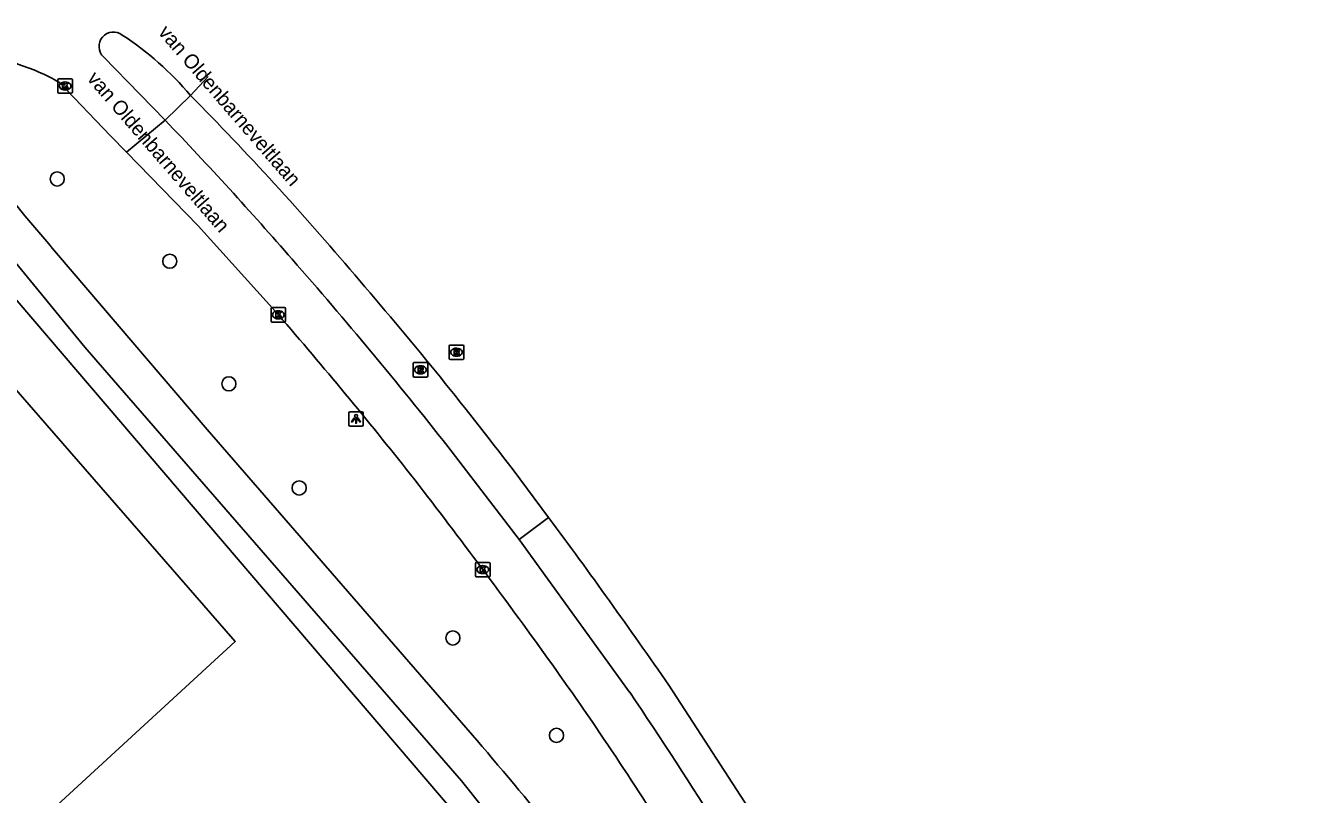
# Model space of a CAD drawing. Extents: x 162417 to 163721, y 384268 to 385416.
# Drawn here: x 163440.1 to 163528.5, y 385162.3 to 385215.4 of the extents above; entities that cross this region are included whole.
import ezdxf

# ---------------------------------------------------------------- set-up
doc = ezdxf.new("R2010")
doc.units = 0
for name, color, linetype in [('IMGEO_Boom', 7, 'Continuous'), ('IMGEO_Fietspad_open', 7, 'Continuous'), ('IMGEO_Gemengd_bos', 7, 'Continuous'), ('IMGEO_Kolk', 7, 'Continuous'), ('IMGEO_Lichtpunt', 7, 'Continuous'), ('IMGEO_Openbare_ruimte_label', 7, 'Continuous'), ('IMGEO_Rijbaan_lokaal_gesloten', 7, 'Continuous'), ('IMGEO_Rijbaan_lokaal_open', 7, 'Continuous'), ('IMGEO_Rioolput', 7, 'Continuous'), ('IMGEO_Verkeerseiland_open', 7, 'Continuous'), ('IMGEO_Voetpad_open', 7, 'Continuous')]:
    doc.layers.add(name, color=color, linetype=linetype)

msp = doc.modelspace()

# ---------------------------------------------------------------- linework, layer by layer
at = {"layer": 'IMGEO_Boom'}
for centre in [(163442.28, 385204.844), (163450.063, 385199.158), (163454.148, 385190.69), (163459.007, 385183.495), (163469.632, 385173.133), (163476.798, 385166.404)]:
    msp.add_circle(centre, 0.489, dxfattribs=at)
at = {"layer": 'IMGEO_Fietspad_open'}
for points in [[(163431.787, 385208.07), (163431.922, 385207.954), (163432.159, 385207.714), (163433.841, 385205.808), (163444.2, 385193.223), (163470.237, 385163.265), (163478.767, 385152.569), (163484.279, 385144.583), (163488.178, 385138.38), (163494.183, 385128.236), (163502.766, 385111.711), (163507.809, 385101.794), (163517.384, 385082.877), (163528.502, 385060.963)], [(163442.24, 385199.707), (163452.646, 385187.546), (163471.281, 385166.067)]]:
    msp.add_lwpolyline(points, dxfattribs=at)
for centre, radius, start, end in [((163733.724, 385447.945), 382.864, 218.38399, 220.41896), ((163318.814, 385033.841), 201.816, 35.81358, 40.93323)]:
    msp.add_arc(centre, radius, start, end, dxfattribs=at)
at = {"layer": 'IMGEO_Gemengd_bos'}
msp.add_lwpolyline([(163309.738, 385096.794), (163334.35, 385105.91), (163401.172, 385130.32), (163403.611, 385131.145), (163408.387, 385133.189), (163412.924, 385135.721), (163417.172, 385138.714), (163421.083, 385142.134), (163454.583, 385172.899), (163428.403, 385202.907)], dxfattribs=at)
at = {"layer": 'IMGEO_Kolk'}
for p, q in [((163442.327, 385210.842), (163442.327, 385211.694)), ((163442.402, 385211.768), (163443.254, 385211.768)), ((163442.815, 385211.548), (163442.84, 385211.548)), ((163443.328, 385211.694), (163443.328, 385210.842)), ((163443.254, 385210.768), (163442.402, 385210.768)), ((163442.838, 385210.988), (163442.813, 385210.988)), ((163457.064, 385195.034), (163457.064, 385195.886)), ((163457.139, 385195.96), (163457.991, 385195.96)), ((163457.552, 385195.74), (163457.577, 385195.74)), ((163458.065, 385195.886), (163458.065, 385195.034)), ((163457.991, 385194.96), (163457.139, 385194.96)), ((163457.575, 385195.18), (163457.55, 385195.18)), ((163471.2, 385177.43), (163471.2, 385178.282)), ((163471.275, 385178.356), (163472.127, 385178.356)), ((163471.688, 385178.136), (163471.713, 385178.136)), ((163472.201, 385178.282), (163472.201, 385177.43)), ((163472.127, 385177.356), (163471.275, 385177.356)), ((163471.711, 385177.576), (163471.686, 385177.576))]:
    msp.add_line(p, q, dxfattribs=at)
for points in [[(163442.327, 385210.842), (163442.327, 385211.694)], [(163442.402, 385211.768), (163443.254, 385211.768)], [(163442.648, 385211.468), (163442.771, 385211.468), (163442.771, 385211.317), (163442.901, 385211.468), (163443.065, 385211.468), (163442.919, 385211.317), (163443.072, 385211.068), (163442.92, 385211.068), (163442.835, 385211.232), (163442.771, 385211.165), (163442.771, 385211.068), (163442.648, 385211.068), (163442.648, 385211.468)], [(163443.328, 385211.694), (163443.328, 385210.842)], [(163443.254, 385210.768), (163442.402, 385210.768)], [(163457.064, 385195.034), (163457.064, 385195.886)], [(163457.139, 385195.96), (163457.991, 385195.96)], [(163457.385, 385195.66), (163457.508, 385195.66), (163457.508, 385195.509), (163457.638, 385195.66), (163457.802, 385195.66), (163457.656, 385195.509), (163457.809, 385195.26), (163457.657, 385195.26), (163457.572, 385195.424), (163457.508, 385195.357), (163457.508, 385195.26), (163457.385, 385195.26), (163457.385, 385195.66)], [(163458.065, 385195.886), (163458.065, 385195.034)], [(163457.991, 385194.96), (163457.139, 385194.96)], [(163471.2, 385177.43), (163471.2, 385178.282)], [(163471.275, 385178.356), (163472.127, 385178.356)], [(163471.521, 385178.056), (163471.644, 385178.056), (163471.644, 385177.905), (163471.774, 385178.056), (163471.938, 385178.056), (163471.792, 385177.905), (163471.945, 385177.656), (163471.793, 385177.656), (163471.708, 385177.82), (163471.644, 385177.753), (163471.644, 385177.656), (163471.521, 385177.656), (163471.521, 385178.056)], [(163472.201, 385178.282), (163472.201, 385177.43)], [(163472.127, 385177.356), (163471.275, 385177.356)]]:
    msp.add_lwpolyline(points, dxfattribs=at)
for centre, start, end in [((163442.404, 385211.692), 91.55205, 178.44795), ((163442.404, 385211.692), 91.55205, 178.44795), ((163443.252, 385211.692), 1.55205, 88.44795), ((163443.252, 385211.692), 1.55205, 88.44795), ((163442.404, 385210.844), 181.55205, 268.44795), ((163442.404, 385210.844), 181.55205, 268.44795), ((163443.252, 385210.844), 271.55205, 358.44795), ((163443.252, 385210.844), 271.55205, 358.44795), ((163457.141, 385195.884), 91.55205, 178.44795), ((163457.141, 385195.884), 91.55205, 178.44795), ((163457.989, 385195.884), 1.55205, 88.44795), ((163457.989, 385195.884), 1.55205, 88.44795), ((163457.141, 385195.036), 181.55205, 268.44795), ((163457.141, 385195.036), 181.55205, 268.44795), ((163457.989, 385195.036), 271.55205, 358.44795), ((163457.989, 385195.036), 271.55205, 358.44795), ((163471.277, 385178.28), 91.55205, 178.44795), ((163471.277, 385178.28), 91.55205, 178.44795), ((163472.125, 385178.28), 1.55205, 88.44795), ((163472.125, 385178.28), 1.55205, 88.44795), ((163471.277, 385177.432), 181.55205, 268.44795), ((163471.277, 385177.432), 181.55205, 268.44795), ((163472.125, 385177.432), 271.55205, 358.44795), ((163472.125, 385177.432), 271.55205, 358.44795)]:
    msp.add_arc(centre, 0.0765, start, end, dxfattribs=at)
for centre, major_axis, ratio, start_param, end_param in [((163442.814, 385211.268), (-0.387, 0.002), 0.722429, 4.712389, 7.853982), ((163442.839, 385211.268), (-0.39, 0.002), 0.717154, 1.570796, 4.712389), ((163457.551, 385195.46), (-0.387, 0.002), 0.722429, 4.712389, 7.853982), ((163457.576, 385195.46), (-0.39, 0.002), 0.717154, 1.570796, 4.712389), ((163471.687, 385177.856), (-0.387, 0.002), 0.722429, 4.712389, 7.853982), ((163471.712, 385177.856), (-0.39, 0.002), 0.717154, 1.570796, 4.712389)]:
    msp.add_ellipse(centre, major_axis=major_axis, ratio=ratio, start_param=start_param, end_param=end_param, dxfattribs=at)
at = {"layer": 'IMGEO_Lichtpunt'}
for p, q in [((163462.441, 385188.67), (163462.441, 385187.863)), ((163462.441, 385188.67), (163462.441, 385187.863)), ((163463.343, 385188.765), (163462.535, 385188.765)), ((163463.343, 385188.765), (163462.535, 385188.765)), ((163463.437, 385187.863), (163463.437, 385188.67)), ((163463.437, 385187.863), (163463.437, 385188.67)), ((163462.535, 385187.769), (163463.343, 385187.769)), ((163462.535, 385187.769), (163463.343, 385187.769))]:
    msp.add_line(p, q, dxfattribs=at)
for points in [[(163462.815, 385188.334), (163462.854, 385188.306), (163462.666, 385188.044), (163462.628, 385188.071), (163462.815, 385188.334)], [(163462.917, 385188.286), (163462.964, 385188.286), (163462.964, 385187.964), (163462.917, 385187.964), (163462.917, 385188.286)], [(163463.027, 385188.306), (163463.065, 385188.333), (163463.252, 385188.071), (163463.213, 385188.043), (163463.027, 385188.306)]]:
    msp.add_lwpolyline(points, dxfattribs=at)
msp.add_circle((163462.94, 385188.468), 0.0994, dxfattribs=at)
for centre, start, end in [((163462.535, 385188.67), 90, 180), ((163462.535, 385188.67), 90, 180), ((163463.343, 385188.67), 0, 90), ((163463.343, 385188.67), 0, 90), ((163462.535, 385187.863), 180, 270), ((163462.535, 385187.863), 180, 270), ((163463.343, 385187.863), 270, 0), ((163463.343, 385187.863), 270, 360)]:
    msp.add_arc(centre, 0.0946, start, end, dxfattribs=at)
at = {"layer": 'IMGEO_Rijbaan_lokaal_gesloten'}
for points in [[(163449.739, 385208.9), (163447.99, 385210.707), (163445.476, 385213.278)], [(163442.441, 385211.502), (163445.973, 385207.812), (163447.069, 385206.687)], [(163452.723, 385211.915), (163451.49, 385210.609)], [(163447.069, 385206.687), (163449.739, 385208.9)], [(163457.568, 385195.458), (163452.027, 385201.595), (163447.069, 385206.687)], [(163474.209, 385179.926), (163469.28, 385186.367)], [(163473.797, 385184.74), (163476.255, 385181.456)], [(163481.855, 385169.387), (163474.209, 385179.926)], [(163484.56, 385169.87), (163490.336, 385160.957)]]:
    msp.add_lwpolyline(points, dxfattribs=at)
for centre, radius, start, end in [((163446.166, 385213.998), 0.997, 52.14455, 226.2035), ((163435.051, 385196.807), 21.465, 40.01748, 56.88472), ((163434.996, 385198.578), 14.915, 60.05669, 72.69854), ((163299.516, 385059.906), 214.027, 40.2589, 44.75949), ((163255.248, 385022.275), 269.548, 41.05077, 43.81761), ((163216.989, 384987.329), 321.352, 38.27073, 41.26975), ((163246.401, 385011.197), 286.053, 37.35006, 40.82901), ((163215.069, 384985.241), 320.931, 38.36418, 40.92118), ((163116.537, 384913.025), 443.033, 35.7928, 37.7783), ((163127.009, 384922.342), 434.871, 34.69434, 36.57258), ((163280.687, 385031.519), 240.583, 32.05663, 35.76633), ((163252.127, 385013.59), 277.575, 31.74698, 34.14439)]:
    msp.add_arc(centre, radius, start, end, dxfattribs=at)
at = {"layer": 'IMGEO_Rijbaan_lokaal_open'}
msp.add_lwpolyline([(163474.209, 385179.926), (163476.255, 385181.456)], dxfattribs=at)
at = {"layer": 'IMGEO_Rioolput'}
for p, q in [((163469.385, 385192.446), (163469.385, 385193.298)), ((163469.46, 385193.372), (163470.312, 385193.372)), ((163469.873, 385193.152), (163469.898, 385193.152)), ((163470.386, 385193.298), (163470.386, 385192.446)), ((163466.891, 385191.234), (163466.891, 385192.086)), ((163466.966, 385192.16), (163467.818, 385192.16)), ((163467.379, 385191.94), (163467.404, 385191.94)), ((163467.892, 385192.086), (163467.892, 385191.234)), ((163470.312, 385192.372), (163469.46, 385192.372)), ((163469.896, 385192.592), (163469.871, 385192.592)), ((163467.818, 385191.16), (163466.966, 385191.16)), ((163467.402, 385191.38), (163467.377, 385191.38))]:
    msp.add_line(p, q, dxfattribs=at)
for points in [[(163469.385, 385192.446), (163469.385, 385193.298)], [(163469.46, 385193.372), (163470.312, 385193.372)], [(163469.974, 385193.07), (163469.722, 385193.072), (163469.722, 385192.672)], [(163469.722, 385192.672), (163469.846, 385192.672), (163469.846, 385192.834), (163469.857, 385192.834)], [(163469.9, 385192.991), (163469.846, 385192.991), (163469.846, 385192.91)], [(163469.846, 385192.91), (163469.898, 385192.91)], [(163469.904, 385192.805), (163469.975, 385192.672), (163470.115, 385192.672), (163470.05, 385192.798)], [(163470.386, 385193.298), (163470.386, 385192.446)], [(163466.891, 385191.234), (163466.891, 385192.086)], [(163466.966, 385192.16), (163467.818, 385192.16)], [(163467.892, 385192.086), (163467.892, 385191.234)], [(163470.312, 385192.372), (163469.46, 385192.372)], [(163467.818, 385191.16), (163466.966, 385191.16)], [(163467.48, 385191.858), (163467.228, 385191.86), (163467.228, 385191.46)], [(163467.228, 385191.46), (163467.352, 385191.46), (163467.352, 385191.622), (163467.363, 385191.622)], [(163467.406, 385191.779), (163467.352, 385191.779), (163467.352, 385191.698)], [(163467.352, 385191.698), (163467.404, 385191.698)], [(163467.41, 385191.593), (163467.481, 385191.46), (163467.621, 385191.46), (163467.556, 385191.586)]]:
    msp.add_lwpolyline(points, dxfattribs=at)
for centre, radius, start, end in [((163469.462, 385193.296), 0.0765, 91.55205, 178.44795), ((163469.462, 385193.296), 0.0765, 91.55205, 178.44795), ((163469.856, 385192.781), 0.0533, 26.02933, 88.69889), ((163469.882, 385193.099), 0.19, 274.7715, 282.96867), ((163469.906, 385192.895), 0.0964, 77.00612, 93.18647), ((163469.92, 385192.952), 0.0378, 276.66336, 79.67722), ((163469.973, 385192.96), 0.109, 350.36119, 89.41601), ((163469.971, 385192.96), 0.112, 277.58423, 350.98172), ((163469.955, 385192.745), 0.108, 29.51342, 73.79051), ((163470.31, 385193.296), 0.0765, 1.55205, 88.44795), ((163470.31, 385193.296), 0.0765, 1.55205, 88.44795), ((163466.968, 385192.084), 0.0765, 91.55205, 178.44795), ((163466.968, 385192.084), 0.0765, 91.55205, 178.44795), ((163467.816, 385192.084), 0.0765, 1.55205, 88.44795), ((163467.816, 385192.084), 0.0765, 1.55205, 88.44795), ((163469.462, 385192.448), 0.0765, 181.55205, 268.44795), ((163469.462, 385192.448), 0.0765, 181.55205, 268.44795), ((163470.31, 385192.448), 0.0765, 271.55205, 358.44795), ((163470.31, 385192.448), 0.0765, 271.55205, 358.44795), ((163466.968, 385191.236), 0.0765, 181.55205, 268.44795), ((163466.968, 385191.236), 0.0765, 181.55205, 268.44795), ((163467.362, 385191.569), 0.0533, 26.02933, 88.69889), ((163467.388, 385191.887), 0.19, 274.7715, 282.96867), ((163467.412, 385191.683), 0.0964, 77.00612, 93.18647), ((163467.426, 385191.74), 0.0378, 276.66336, 79.67722), ((163467.479, 385191.748), 0.109, 350.36119, 89.41601), ((163467.477, 385191.748), 0.112, 277.58423, 350.98172), ((163467.461, 385191.533), 0.108, 29.51342, 73.79051), ((163467.816, 385191.236), 0.0765, 271.55205, 358.44795), ((163467.816, 385191.236), 0.0765, 271.55205, 358.44795)]:
    msp.add_arc(centre, radius, start, end, dxfattribs=at)
for centre, major_axis, ratio, start_param, end_param in [((163469.872, 385192.872), (-0.387, 0.002), 0.722429, 4.712389, 7.853982), ((163469.897, 385192.872), (-0.39, 0.002), 0.717154, 1.570796, 4.712389), ((163467.378, 385191.66), (-0.387, 0.002), 0.722429, 4.712389, 7.853982), ((163467.403, 385191.66), (-0.39, 0.002), 0.717154, 1.570796, 4.712389)]:
    msp.add_ellipse(centre, major_axis=major_axis, ratio=ratio, start_param=start_param, end_param=end_param, dxfattribs=at)
at = {"layer": 'IMGEO_Verkeerseiland_open'}
msp.add_lwpolyline([(163451.49, 385210.609), (163449.739, 385208.9)], dxfattribs=at)
at = {"layer": 'IMGEO_Voetpad_open'}
msp.add_lwpolyline([(163469.791, 385161.005), (163431.516, 385205.744)], dxfattribs=at)

# ---------------------------------------------------------------- texts
at = {"layer": 'IMGEO_Openbare_ruimte_label'}
for rotation, p in [(310.82494, (163449.213, 385214.939)), (310.86241, (163444.291, 385211.74))]:
    msp.add_text('van Oldenbarneveltlaan', height=1, rotation=rotation, dxfattribs=at).set_placement(p)

doc.saveas('drawing.dxf')
